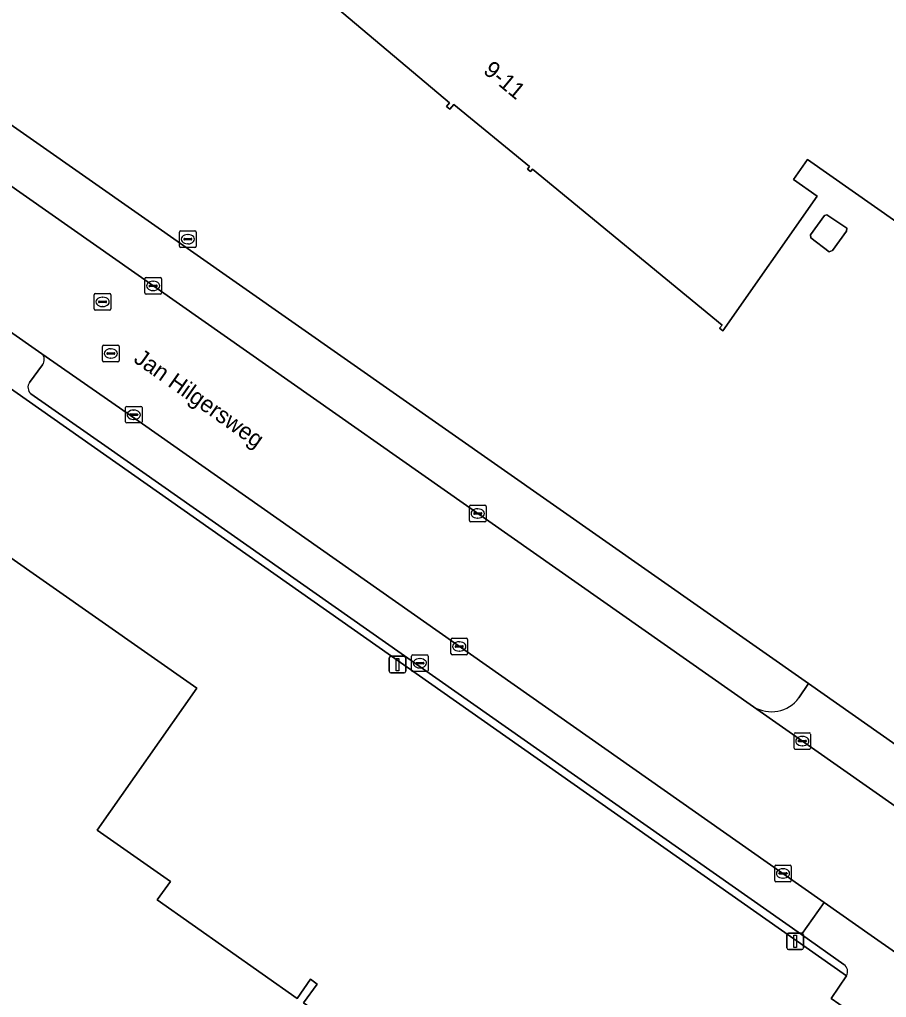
# Model space of a CAD drawing. Extents: x 155018 to 156648, y 383979 to 385733.
# Drawn here: x 155390.3 to 155442.6, y 384762.6 to 384821.5 of the extents above; entities that cross this region are included whole.
import ezdxf

# ---------------------------------------------------------------- set-up
doc = ezdxf.new("R2010")
doc.units = 0
for name, color, linetype in [('IMGEO_Brandkraan', 7, 'Continuous'), ('IMGEO_Erf', 7, 'Continuous'), ('IMGEO_Kolk', 7, 'Continuous'), ('IMGEO_Lichtmast', 7, 'Continuous'), ('IMGEO_Openbare_ruimte_label', 7, 'Continuous'), ('IMGEO_Pand', 7, 'Continuous'), ('IMGEO_Pand_nummerreeks', 7, 'Continuous'), ('IMGEO_Parkeervlak_open', 7, 'Continuous'), ('IMGEO_Rijbaan_lokaal_gesloten', 7, 'Continuous'), ('IMGEO_Rioolput', 7, 'Continuous'), ('IMGEO_Voetpad_open', 7, 'Continuous')]:
    doc.layers.add(name, color=color, linetype=linetype)

msp = doc.modelspace()

# ---------------------------------------------------------------- linework, layer by layer
at = {"layer": 'IMGEO_Brandkraan'}
for p, q in [((155413.941, 384782.303), (155413.941, 384783.155)), ((155414.016, 384783.229), (155414.868, 384783.229)), ((155414.2, 384782.723), (155414.2, 384782.735)), ((155414.638, 384782.686), (155414.24, 384782.686)), ((155414.243, 384782.772), (155414.641, 384782.772)), ((155414.429, 384783.009), (155414.454, 384783.009)), ((155414.684, 384782.735), (155414.684, 384782.723)), ((155414.942, 384783.155), (155414.942, 384782.303)), ((155414.868, 384782.229), (155414.016, 384782.229)), ((155414.452, 384782.449), (155414.427, 384782.449))]:
    msp.add_line(p, q, dxfattribs=at)
for points in [[(155413.941, 384782.303), (155413.941, 384783.155)], [(155414.016, 384783.229), (155414.868, 384783.229)], [(155414.942, 384783.155), (155414.942, 384782.303)], [(155414.868, 384782.229), (155414.016, 384782.229)]]:
    msp.add_lwpolyline(points, dxfattribs=at)
for centre, radius, start, end in [((155414.018, 384783.153), 0.0765, 91.55205, 178.44795), ((155414.018, 384783.153), 0.0765, 91.55205, 178.44795), ((155414.24, 384782.732), 0.0403, 85.87752, 175.75265), ((155414.237, 384782.722), 0.0366, 178.93798, 274.71019), ((155414.641, 384782.729), 0.043, 264.86636, 352.45326), ((155414.645, 384782.734), 0.0386, 1.73085, 96.63898), ((155414.866, 384783.153), 0.0765, 1.55205, 88.44795), ((155414.866, 384783.153), 0.0765, 1.55205, 88.44795), ((155414.018, 384782.305), 0.0765, 181.55205, 268.44795), ((155414.018, 384782.305), 0.0765, 181.55205, 268.44795), ((155414.866, 384782.305), 0.0765, 271.55205, 358.44795), ((155414.866, 384782.305), 0.0765, 271.55205, 358.44795)]:
    msp.add_arc(centre, radius, start, end, dxfattribs=at)
for centre, major_axis, ratio, start_param, end_param in [((155414.428, 384782.729), (-0.387, 0.002), 0.722429, 4.712389, 7.853982), ((155414.453, 384782.729), (-0.39, 0.002), 0.717154, 1.570796, 4.712389)]:
    msp.add_ellipse(centre, major_axis=major_axis, ratio=ratio, start_param=start_param, end_param=end_param, dxfattribs=at)
at = {"layer": 'IMGEO_Erf'}
for points in [[(155500, 384852.57), (155544.63, 384821.302), (155508.467, 384769.69), (155505.598, 384765.595), (155500, 384769.517), (155480.059, 384783.489), (155482.392, 384786.812), (155457.825, 384804.026), (155455.513, 384800.688), (155437.8, 384813.099), (155436.96, 384811.899), (155438.396, 384810.891), (155432.697, 384802.767), (155432.495, 384802.926), (155432.66, 384803.115), (155421.239, 384812.515), (155421.118, 384812.365), (155420.922, 384812.517), (155421.048, 384812.673), (155416.493, 384816.423), (155416.246, 384816.122), (155416.038, 384816.294), (155416.222, 384816.518), (155403.487, 384827.271)], [(155341.136, 384849.344), (155357.104, 384838.097), (155388.182, 384816.31), (155437.864, 384781.52), (155468.111, 384760.264), (155482.743, 384750), (155497.007, 384739.994), (155500, 384737.848), (155500.185, 384737.718), (155505.292, 384734.131), (155525.191, 384720.19), (155529.43, 384717.209), (155537.244, 384711.718), (155537.392, 384711.902)], [(155455.525, 384753.704), (155455.245, 384753.973), (155451.096, 384756.854), (155449.87, 384755.133), (155439.233, 384762.528), (155440.155, 384763.897), (155361.769, 384818.945), (155361.486, 384818.938), (155361.268, 384818.932), (155354.808, 384823.467)], [(155380.295, 384795.715), (155400.987, 384781.219), (155394.985, 384772.673), (155399.401, 384769.578), (155398.613, 384768.476), (155407.047, 384762.521), (155407.847, 384763.684), (155408.247, 384763.388), (155407.436, 384762.27), (155415.863, 384756.329), (155416.674, 384757.499), (155421.517, 384754.124), (155418.633, 384750), (155401.505, 384725.502), (155370.384, 384747.304)]]:
    msp.add_lwpolyline(points, dxfattribs=at)
msp.add_lwpolyline([(155439.31, 384807.607), (155439.12, 384807.535), (155438.006, 384808.38), (155437.982, 384808.563), (155438.826, 384809.73), (155438.981, 384809.767), (155440.174, 384808.964), (155440.164, 384808.775)], close=True, dxfattribs=at)
at = {"layer": 'IMGEO_Kolk'}
for p, q in [((155397.862, 384805.051), (155397.862, 384805.903)), ((155397.937, 384805.977), (155398.789, 384805.977)), ((155398.35, 384805.757), (155398.375, 384805.757)), ((155398.863, 384805.903), (155398.863, 384805.051)), ((155398.121, 384805.471), (155398.121, 384805.483)), ((155398.559, 384805.434), (155398.161, 384805.434)), ((155398.164, 384805.52), (155398.562, 384805.52)), ((155398.373, 384805.197), (155398.348, 384805.197)), ((155398.605, 384805.483), (155398.605, 384805.471)), ((155398.789, 384804.977), (155397.937, 384804.977)), ((155396.694, 384797.288), (155396.694, 384798.14)), ((155396.769, 384798.214), (155397.621, 384798.214)), ((155397.182, 384797.994), (155397.207, 384797.994)), ((155397.695, 384798.14), (155397.695, 384797.288)), ((155396.953, 384797.708), (155396.953, 384797.72)), ((155397.391, 384797.671), (155396.993, 384797.671)), ((155396.996, 384797.757), (155397.394, 384797.757)), ((155397.205, 384797.434), (155397.18, 384797.434)), ((155397.437, 384797.72), (155397.437, 384797.708)), ((155397.621, 384797.214), (155396.769, 384797.214)), ((155417.428, 384791.333), (155417.428, 384792.185)), ((155417.503, 384792.259), (155418.355, 384792.259)), ((155418.429, 384792.185), (155418.429, 384791.333)), ((155417.687, 384791.753), (155417.687, 384791.765)), ((155418.125, 384791.716), (155417.727, 384791.716)), ((155417.73, 384791.802), (155418.128, 384791.802)), ((155417.916, 384792.039), (155417.941, 384792.039)), ((155418.171, 384791.765), (155418.171, 384791.753)), ((155418.355, 384791.259), (155417.503, 384791.259)), ((155417.939, 384791.479), (155417.914, 384791.479)), ((155416.316, 384783.316), (155416.316, 384784.168)), ((155416.391, 384784.242), (155417.243, 384784.242)), ((155416.804, 384784.022), (155416.829, 384784.022)), ((155417.317, 384784.168), (155417.317, 384783.316)), ((155417.243, 384783.242), (155416.391, 384783.242)), ((155416.575, 384783.736), (155416.575, 384783.748)), ((155417.013, 384783.699), (155416.615, 384783.699)), ((155416.618, 384783.785), (155417.016, 384783.785)), ((155416.827, 384783.462), (155416.802, 384783.462)), ((155417.059, 384783.748), (155417.059, 384783.736)), ((155437.069, 384778.54), (155437.921, 384778.54)), ((155436.994, 384777.614), (155436.994, 384778.466)), ((155437.253, 384778.034), (155437.253, 384778.046)), ((155437.691, 384777.997), (155437.293, 384777.997)), ((155437.296, 384778.083), (155437.694, 384778.083)), ((155437.482, 384778.32), (155437.507, 384778.32)), ((155437.737, 384778.046), (155437.737, 384778.034)), ((155437.995, 384778.466), (155437.995, 384777.614)), ((155437.921, 384777.54), (155437.069, 384777.54)), ((155437.505, 384777.76), (155437.48, 384777.76)), ((155435.829, 384769.636), (155435.829, 384770.488)), ((155435.904, 384770.562), (155436.756, 384770.562)), ((155436.317, 384770.342), (155436.342, 384770.342)), ((155436.83, 384770.488), (155436.83, 384769.636)), ((155436.088, 384770.056), (155436.088, 384770.068)), ((155436.526, 384770.019), (155436.128, 384770.019)), ((155436.131, 384770.105), (155436.529, 384770.105)), ((155436.34, 384769.782), (155436.315, 384769.782)), ((155436.572, 384770.068), (155436.572, 384770.056)), ((155436.756, 384769.562), (155435.904, 384769.562))]:
    msp.add_line(p, q, dxfattribs=at)
for points in [[(155397.862, 384805.051), (155397.862, 384805.903)], [(155397.937, 384805.977), (155398.789, 384805.977)], [(155398.863, 384805.903), (155398.863, 384805.051)], [(155398.789, 384804.977), (155397.937, 384804.977)], [(155396.694, 384797.288), (155396.694, 384798.14)], [(155396.769, 384798.214), (155397.621, 384798.214)], [(155397.695, 384798.14), (155397.695, 384797.288)], [(155397.621, 384797.214), (155396.769, 384797.214)], [(155417.428, 384791.333), (155417.428, 384792.185)], [(155417.503, 384792.259), (155418.355, 384792.259)], [(155418.429, 384792.185), (155418.429, 384791.333)], [(155418.355, 384791.259), (155417.503, 384791.259)], [(155416.316, 384783.316), (155416.316, 384784.168)], [(155416.391, 384784.242), (155417.243, 384784.242)], [(155417.317, 384784.168), (155417.317, 384783.316)], [(155417.243, 384783.242), (155416.391, 384783.242)], [(155437.069, 384778.54), (155437.921, 384778.54)], [(155436.994, 384777.614), (155436.994, 384778.466)], [(155437.995, 384778.466), (155437.995, 384777.614)], [(155437.921, 384777.54), (155437.069, 384777.54)], [(155435.829, 384769.636), (155435.829, 384770.488)], [(155435.904, 384770.562), (155436.756, 384770.562)], [(155436.83, 384770.488), (155436.83, 384769.636)], [(155436.756, 384769.562), (155435.904, 384769.562)]]:
    msp.add_lwpolyline(points, dxfattribs=at)
for centre, radius, start, end in [((155397.939, 384805.901), 0.0765, 91.55205, 178.44795), ((155397.939, 384805.901), 0.0765, 91.55205, 178.44795), ((155398.787, 384805.901), 0.0765, 1.55205, 88.44795), ((155398.787, 384805.901), 0.0765, 1.55205, 88.44795), ((155397.939, 384805.053), 0.0765, 181.55205, 268.44795), ((155397.939, 384805.053), 0.0765, 181.55205, 268.44795), ((155398.161, 384805.48), 0.0403, 85.87752, 175.75265), ((155398.158, 384805.47), 0.0366, 178.93798, 274.71019), ((155398.562, 384805.477), 0.043, 264.86636, 352.45326), ((155398.566, 384805.482), 0.0386, 1.73085, 96.63898), ((155398.787, 384805.053), 0.0765, 271.55205, 358.44795), ((155398.787, 384805.053), 0.0765, 271.55205, 358.44795), ((155396.771, 384798.138), 0.0765, 91.55205, 178.44795), ((155396.771, 384798.138), 0.0765, 91.55205, 178.44795), ((155397.619, 384798.138), 0.0765, 1.55205, 88.44795), ((155397.619, 384798.138), 0.0765, 1.55205, 88.44795), ((155396.993, 384797.717), 0.0403, 85.87752, 175.75265), ((155396.99, 384797.707), 0.0366, 178.93798, 274.71019), ((155397.394, 384797.714), 0.043, 264.86636, 352.45326), ((155397.398, 384797.719), 0.0386, 1.73085, 96.63898), ((155396.771, 384797.29), 0.0765, 181.55205, 268.44795), ((155396.771, 384797.29), 0.0765, 181.55205, 268.44795), ((155397.619, 384797.29), 0.0765, 271.55205, 358.44795), ((155397.619, 384797.29), 0.0765, 271.55205, 358.44795), ((155417.505, 384792.183), 0.0765, 91.55205, 178.44795), ((155417.505, 384792.183), 0.0765, 91.55205, 178.44795), ((155418.353, 384792.183), 0.0765, 1.55205, 88.44795), ((155418.353, 384792.183), 0.0765, 1.55205, 88.44795), ((155417.727, 384791.762), 0.0403, 85.87752, 175.75265), ((155417.724, 384791.752), 0.0366, 178.93798, 274.71019), ((155418.128, 384791.759), 0.043, 264.86636, 352.45326), ((155418.132, 384791.764), 0.0386, 1.73085, 96.63898), ((155417.505, 384791.335), 0.0765, 181.55205, 268.44795), ((155417.505, 384791.335), 0.0765, 181.55205, 268.44795), ((155418.353, 384791.335), 0.0765, 271.55205, 358.44795), ((155418.353, 384791.335), 0.0765, 271.55205, 358.44795), ((155416.393, 384784.166), 0.0765, 91.55205, 178.44795), ((155416.393, 384784.166), 0.0765, 91.55205, 178.44795), ((155417.241, 384784.166), 0.0765, 1.55205, 88.44795), ((155417.241, 384784.166), 0.0765, 1.55205, 88.44795), ((155416.393, 384783.318), 0.0765, 181.55205, 268.44795), ((155416.393, 384783.318), 0.0765, 181.55205, 268.44795), ((155416.615, 384783.745), 0.0403, 85.87752, 175.75265), ((155416.612, 384783.735), 0.0366, 178.93798, 274.71019), ((155417.016, 384783.742), 0.043, 264.86636, 352.45326), ((155417.02, 384783.747), 0.0386, 1.73085, 96.63898), ((155417.241, 384783.318), 0.0765, 271.55205, 358.44795), ((155417.241, 384783.318), 0.0765, 271.55205, 358.44795), ((155437.071, 384778.464), 0.0765, 91.55205, 178.44795), ((155437.071, 384778.464), 0.0765, 91.55205, 178.44795), ((155437.919, 384778.464), 0.0765, 1.55205, 88.44795), ((155437.919, 384778.464), 0.0765, 1.55205, 88.44795), ((155437.293, 384778.043), 0.0403, 85.87752, 175.75265), ((155437.29, 384778.033), 0.0366, 178.93798, 274.71019), ((155437.694, 384778.04), 0.043, 264.86636, 352.45326), ((155437.698, 384778.045), 0.0386, 1.73085, 96.63898), ((155437.071, 384777.616), 0.0765, 181.55205, 268.44795), ((155437.071, 384777.616), 0.0765, 181.55205, 268.44795), ((155437.919, 384777.616), 0.0765, 271.55205, 358.44795), ((155437.919, 384777.616), 0.0765, 271.55205, 358.44795), ((155435.906, 384770.486), 0.0765, 91.55205, 178.44795), ((155435.906, 384770.486), 0.0765, 91.55205, 178.44795), ((155436.754, 384770.486), 0.0765, 1.55205, 88.44795), ((155436.754, 384770.486), 0.0765, 1.55205, 88.44795), ((155436.128, 384770.065), 0.0403, 85.87752, 175.75265), ((155436.125, 384770.055), 0.0366, 178.93798, 274.71019), ((155436.529, 384770.062), 0.043, 264.86636, 352.45326), ((155436.533, 384770.067), 0.0386, 1.73085, 96.63898), ((155435.906, 384769.638), 0.0765, 181.55205, 268.44795), ((155435.906, 384769.638), 0.0765, 181.55205, 268.44795), ((155436.754, 384769.638), 0.0765, 271.55205, 358.44795), ((155436.754, 384769.638), 0.0765, 271.55205, 358.44795)]:
    msp.add_arc(centre, radius, start, end, dxfattribs=at)
for centre, major_axis, ratio, start_param, end_param in [((155398.349, 384805.477), (-0.387, 0.002), 0.722429, 4.712389, 7.853982), ((155398.374, 384805.477), (-0.39, 0.002), 0.717154, 1.570796, 4.712389), ((155397.181, 384797.714), (-0.387, 0.002), 0.722429, 4.712389, 7.853982), ((155397.206, 384797.714), (-0.39, 0.002), 0.717154, 1.570796, 4.712389), ((155417.915, 384791.759), (-0.387, 0.002), 0.722429, 4.712389, 7.853982), ((155417.94, 384791.759), (-0.39, 0.002), 0.717154, 1.570796, 4.712389), ((155416.803, 384783.742), (-0.387, 0.002), 0.722429, 4.712389, 7.853982), ((155416.828, 384783.742), (-0.39, 0.002), 0.717154, 1.570796, 4.712389), ((155437.481, 384778.04), (-0.387, 0.002), 0.722429, 4.712389, 7.853982), ((155437.506, 384778.04), (-0.39, 0.002), 0.717154, 1.570796, 4.712389), ((155436.316, 384770.062), (-0.387, 0.002), 0.722429, 4.712389, 7.853982), ((155436.341, 384770.062), (-0.39, 0.002), 0.717154, 1.570796, 4.712389)]:
    msp.add_ellipse(centre, major_axis=major_axis, ratio=ratio, start_param=start_param, end_param=end_param, dxfattribs=at)
at = {"layer": 'IMGEO_Lichtmast'}
for p, q in [((155412.596, 384782.248), (155412.596, 384783.048)), ((155412.596, 384783.048), (155412.596, 384782.248)), ((155412.696, 384783.148), (155413.486, 384783.148)), ((155413.486, 384783.148), (155412.696, 384783.148)), ((155413.586, 384783.048), (155413.586, 384782.248)), ((155413.586, 384782.248), (155413.586, 384783.048)), ((155413.486, 384782.148), (155412.696, 384782.148)), ((155412.696, 384782.148), (155413.486, 384782.148)), ((155436.567, 384765.568), (155436.567, 384766.368)), ((155436.567, 384766.368), (155436.567, 384765.568)), ((155436.667, 384766.468), (155437.457, 384766.468)), ((155437.457, 384766.468), (155436.667, 384766.468)), ((155437.557, 384766.368), (155437.557, 384765.568)), ((155437.557, 384765.568), (155437.557, 384766.368)), ((155437.457, 384765.468), (155436.667, 384765.468)), ((155436.667, 384765.468), (155437.457, 384765.468))]:
    msp.add_line(p, q, dxfattribs=at)
for points in [[(155413.016, 384783.023), (155413.166, 384783.023), (155413.166, 384782.273), (155413.016, 384782.273), (155413.016, 384783.023)], [(155436.987, 384766.343), (155437.137, 384766.343), (155437.137, 384765.593), (155436.987, 384765.593), (155436.987, 384766.343)]]:
    msp.add_lwpolyline(points, dxfattribs=at)
for centre, start, end in [((155412.696, 384783.048), 90, 180), ((155412.696, 384783.048), 90, 180), ((155413.486, 384783.048), 0, 90), ((155413.486, 384783.048), 360, 90), ((155412.696, 384782.248), 180, 270), ((155412.696, 384782.248), 180, 270), ((155413.486, 384782.248), 270, 0), ((155413.486, 384782.248), 270, 0), ((155436.667, 384766.368), 90, 180), ((155436.667, 384766.368), 90, 180), ((155437.457, 384766.368), 0, 90), ((155437.457, 384766.368), 360, 90), ((155436.667, 384765.568), 180, 270), ((155436.667, 384765.568), 180, 270), ((155437.457, 384765.568), 270, 0), ((155437.457, 384765.568), 270, 0)]:
    msp.add_arc(centre, 0.1, start, end, dxfattribs=at)
at = {"layer": 'IMGEO_Pand'}
for points in [[(155403.487, 384827.271), (155416.222, 384816.518), (155416.038, 384816.294), (155416.246, 384816.122), (155416.493, 384816.423), (155421.048, 384812.673), (155420.922, 384812.517), (155421.118, 384812.365), (155421.239, 384812.515), (155432.66, 384803.115), (155432.495, 384802.926), (155432.697, 384802.767), (155438.396, 384810.891), (155436.96, 384811.899), (155437.8, 384813.099), (155455.513, 384800.688), (155457.825, 384804.026), (155482.392, 384786.812), (155480.059, 384783.489), (155500, 384769.517), (155505.598, 384765.595), (155508.467, 384769.69), (155544.63, 384821.302), (155500, 384852.57)], [(155370.384, 384747.304), (155401.505, 384725.502), (155418.633, 384750), (155421.517, 384754.124), (155416.674, 384757.499), (155415.863, 384756.329), (155407.436, 384762.27), (155408.247, 384763.388), (155407.847, 384763.684), (155407.047, 384762.521), (155398.613, 384768.476), (155399.401, 384769.578), (155394.985, 384772.673), (155400.987, 384781.219), (155380.295, 384795.715)]]:
    msp.add_lwpolyline(points, dxfattribs=at)
msp.add_lwpolyline([(155439.12, 384807.535), (155439.31, 384807.607), (155440.164, 384808.775), (155440.174, 384808.964), (155438.981, 384809.767), (155438.826, 384809.73), (155437.982, 384808.563), (155438.006, 384808.38)], close=True, dxfattribs=at)
at = {"layer": 'IMGEO_Parkeervlak_open'}
for points in [[(155397.713, 384797.165), (155391.658, 384801.391)], [(155391.693, 384800.729), (155390.91, 384799.662)], [(155390.997, 384798.97), (155395.651, 384795.72), (155437.436, 384766.376), (155438.804, 384768.318), (155436.329, 384770.061), (155397.713, 384797.165)]]:
    msp.add_lwpolyline(points, dxfattribs=at)
for centre, radius, start, end in [((155391.302, 384801.04), 0.5, 321.4917, 44.56113), ((155391.335, 384799.364), 0.519, 144.96102, 229.37053)]:
    msp.add_arc(centre, radius, start, end, dxfattribs=at)
at = {"layer": 'IMGEO_Rijbaan_lokaal_gesloten'}
for points in [[(155494.889, 384737.794), (155477.483, 384750), (155467.973, 384756.67), (155434.551, 384780.106), (155388.019, 384812.731), (155353.81, 384836.716)], [(155356.562, 384825.996), (155363.162, 384821.376), (155382.366, 384807.915), (155389.497, 384802.9), (155391.658, 384801.391), (155397.713, 384797.165), (155436.329, 384770.061), (155438.804, 384768.318), (155441.642, 384766.318), (155456.242, 384756.107), (155456.592, 384755.849), (155464.924, 384750), (155479.512, 384739.757), (155484.418, 384736.312)]]:
    msp.add_lwpolyline(points, dxfattribs=at)
at = {"layer": 'IMGEO_Rioolput'}
for p, q in [((155399.956, 384807.868), (155399.956, 384808.72)), ((155400.031, 384808.794), (155400.883, 384808.794)), ((155400.957, 384808.72), (155400.957, 384807.868)), ((155400.215, 384808.288), (155400.215, 384808.3)), ((155400.653, 384808.251), (155400.255, 384808.251)), ((155400.258, 384808.337), (155400.656, 384808.337)), ((155400.467, 384808.014), (155400.442, 384808.014)), ((155400.444, 384808.574), (155400.469, 384808.574)), ((155400.699, 384808.3), (155400.699, 384808.288)), ((155400.883, 384807.794), (155400.031, 384807.794)), ((155394.815, 384804.089), (155394.815, 384804.941)), ((155394.89, 384805.015), (155395.742, 384805.015)), ((155395.074, 384804.509), (155395.074, 384804.521)), ((155395.512, 384804.472), (155395.114, 384804.472)), ((155395.117, 384804.558), (155395.515, 384804.558)), ((155395.303, 384804.795), (155395.328, 384804.795)), ((155395.558, 384804.521), (155395.558, 384804.509)), ((155395.816, 384804.941), (155395.816, 384804.089)), ((155395.742, 384804.015), (155394.89, 384804.015)), ((155395.326, 384804.235), (155395.301, 384804.235)), ((155395.311, 384800.978), (155395.311, 384801.83)), ((155395.386, 384801.904), (155396.238, 384801.904)), ((155395.799, 384801.684), (155395.824, 384801.684)), ((155396.312, 384801.83), (155396.312, 384800.978)), ((155395.57, 384801.398), (155395.57, 384801.41)), ((155396.008, 384801.361), (155395.61, 384801.361)), ((155395.613, 384801.447), (155396.011, 384801.447)), ((155395.822, 384801.124), (155395.797, 384801.124)), ((155396.054, 384801.41), (155396.054, 384801.398)), ((155396.238, 384800.904), (155395.386, 384800.904))]:
    msp.add_line(p, q, dxfattribs=at)
for points in [[(155399.956, 384807.868), (155399.956, 384808.72)], [(155400.031, 384808.794), (155400.883, 384808.794)], [(155400.957, 384808.72), (155400.957, 384807.868)], [(155400.883, 384807.794), (155400.031, 384807.794)], [(155394.815, 384804.089), (155394.815, 384804.941)], [(155394.89, 384805.015), (155395.742, 384805.015)], [(155395.816, 384804.941), (155395.816, 384804.089)], [(155395.742, 384804.015), (155394.89, 384804.015)], [(155395.311, 384800.978), (155395.311, 384801.83)], [(155395.386, 384801.904), (155396.238, 384801.904)], [(155396.312, 384801.83), (155396.312, 384800.978)], [(155396.238, 384800.904), (155395.386, 384800.904)]]:
    msp.add_lwpolyline(points, dxfattribs=at)
for centre, radius, start, end in [((155400.033, 384808.718), 0.0765, 91.55205, 178.44795), ((155400.033, 384808.718), 0.0765, 91.55205, 178.44795), ((155400.881, 384808.718), 0.0765, 1.55205, 88.44795), ((155400.881, 384808.718), 0.0765, 1.55205, 88.44795), ((155400.255, 384808.297), 0.0403, 85.87752, 175.75265), ((155400.252, 384808.287), 0.0366, 178.93798, 274.71019), ((155400.656, 384808.294), 0.043, 264.86636, 352.45326), ((155400.66, 384808.299), 0.0386, 1.73085, 96.63898), ((155400.033, 384807.87), 0.0765, 181.55205, 268.44795), ((155400.033, 384807.87), 0.0765, 181.55205, 268.44795), ((155400.881, 384807.87), 0.0765, 271.55205, 358.44795), ((155400.881, 384807.87), 0.0765, 271.55205, 358.44795), ((155394.892, 384804.939), 0.0765, 91.55205, 178.44795), ((155394.892, 384804.939), 0.0765, 91.55205, 178.44795), ((155395.114, 384804.518), 0.0403, 85.87752, 175.75265), ((155395.111, 384804.508), 0.0366, 178.93798, 274.71019), ((155395.515, 384804.515), 0.043, 264.86636, 352.45326), ((155395.519, 384804.52), 0.0386, 1.73085, 96.63898), ((155395.74, 384804.939), 0.0765, 1.55205, 88.44795), ((155395.74, 384804.939), 0.0765, 1.55205, 88.44795), ((155394.892, 384804.091), 0.0765, 181.55205, 268.44795), ((155394.892, 384804.091), 0.0765, 181.55205, 268.44795), ((155395.74, 384804.091), 0.0765, 271.55205, 358.44795), ((155395.74, 384804.091), 0.0765, 271.55205, 358.44795), ((155395.388, 384801.828), 0.0765, 91.55205, 178.44795), ((155395.388, 384801.828), 0.0765, 91.55205, 178.44795), ((155396.236, 384801.828), 0.0765, 1.55205, 88.44795), ((155396.236, 384801.828), 0.0765, 1.55205, 88.44795), ((155395.388, 384800.98), 0.0765, 181.55205, 268.44795), ((155395.388, 384800.98), 0.0765, 181.55205, 268.44795), ((155395.61, 384801.407), 0.0403, 85.87752, 175.75265), ((155395.607, 384801.397), 0.0366, 178.93798, 274.71019), ((155396.011, 384801.404), 0.043, 264.86636, 352.45326), ((155396.015, 384801.409), 0.0386, 1.73085, 96.63898), ((155396.236, 384800.98), 0.0765, 271.55205, 358.44795), ((155396.236, 384800.98), 0.0765, 271.55205, 358.44795)]:
    msp.add_arc(centre, radius, start, end, dxfattribs=at)
for centre, major_axis, ratio, start_param, end_param in [((155400.443, 384808.294), (-0.387, 0.002), 0.722429, 4.712389, 7.853982), ((155400.468, 384808.294), (-0.39, 0.002), 0.717154, 1.570796, 4.712389), ((155395.302, 384804.515), (-0.387, 0.002), 0.722429, 4.712389, 7.853982), ((155395.327, 384804.515), (-0.39, 0.002), 0.717154, 1.570796, 4.712389), ((155395.798, 384801.404), (-0.387, 0.002), 0.722429, 4.712389, 7.853982), ((155395.823, 384801.404), (-0.39, 0.002), 0.717154, 1.570796, 4.712389)]:
    msp.add_ellipse(centre, major_axis=major_axis, ratio=ratio, start_param=start_param, end_param=end_param, dxfattribs=at)
at = {"layer": 'IMGEO_Voetpad_open'}
for points in [[(155362.067, 384818.93), (155361.769, 384818.945), (155440.155, 384763.897)], [(155437.289, 384780.642), (155437.864, 384781.52), (155388.182, 384816.31), (155387.591, 384815.488)], [(155388.019, 384812.731), (155434.551, 384780.106)], [(155391.658, 384801.391), (155389.497, 384802.9)], [(155390.91, 384799.662), (155391.693, 384800.729)], [(155440.005, 384764.572), (155437.436, 384766.376), (155395.651, 384795.72), (155390.997, 384798.97)], [(155467.515, 384759.441), (155468.111, 384760.264), (155437.864, 384781.52), (155437.289, 384780.642)], [(155434.551, 384780.106), (155467.973, 384756.67)], [(155441.642, 384766.318), (155438.804, 384768.318), (155437.436, 384766.376), (155440.005, 384764.572)], [(155440.155, 384763.897), (155439.233, 384762.528), (155449.87, 384755.133), (155451.096, 384756.854), (155455.245, 384753.973), (155456.592, 384755.849), (155456.242, 384756.107), (155441.642, 384766.318)]]:
    msp.add_lwpolyline(points, dxfattribs=at)
for centre, radius, start, end in [((155391.302, 384801.04), 0.5, 321.4917, 44.56113), ((155391.335, 384799.364), 0.519, 144.96102, 229.37053), ((155435.623, 384781.889), 2.08, 238.96996, 323.18271), ((155435.623, 384781.889), 2.08, 238.96996, 323.18271), ((155439.703, 384764.151), 0.518, 330.70332, 54.35429), ((155439.703, 384764.151), 0.518, 330.70332, 54.35429)]:
    msp.add_arc(centre, radius, start, end, dxfattribs=at)

# ---------------------------------------------------------------- texts
at = {"layer": 'IMGEO_Openbare_ruimte_label'}
msp.add_text('Jan Hilgersweg', height=1, rotation=324.76864, dxfattribs=at).set_placement((155397.121, 384800.936))
at = {"layer": 'IMGEO_Pand_nummerreeks'}
msp.add_text('9-11', height=1, rotation=320.37424, dxfattribs=at).set_placement((155418.203, 384818.358))

doc.saveas('drawing.dxf')
